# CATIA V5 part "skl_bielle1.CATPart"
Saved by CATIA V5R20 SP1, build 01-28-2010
Part number: skl_bielle1
Publications: "Droite.1", "Droite.2", "Droite.3", "Plan xy"
Bounding box of the stored display mesh (mm): x 443.544 to 475.437, y 911.835 to 1006.613, z -100 to 0
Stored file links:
  C:\Users\Manon\Desktop\IAO\SKL_rlanglais\skl_bielle1.CATPart
  C:\Users\Manon\Desktop\IAO\SKL_rlanglais\SKL_rlanglais.CATProduct
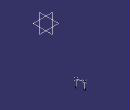
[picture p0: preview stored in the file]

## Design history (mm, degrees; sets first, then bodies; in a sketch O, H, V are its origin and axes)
Set1
  Point1 "A": linked copy from another document
  Point2 "B": linked copy from another document
Set2
  Line1: type PtPt, FirstPoint Point1, SecondPoint Point2
  Line2: type Normal, RefPoint Point1, RefSkin xy-plane, Start 0, End 100
  Line3: type Normal, RefPoint Point2, RefSkin xy-plane, Start 0, End 100
Body1 (main body)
